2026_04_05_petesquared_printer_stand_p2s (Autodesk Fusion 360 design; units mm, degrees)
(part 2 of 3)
sketch "printer_shelf_top" plane through (0, 0, 0) normal (0, 0, 1) x axis (1, 0, 0)
  line L1 (214.249, 477.012) -> (-214.249, 477.012)
  line L2 (214.249, 0) -> (214.249, 477.012)
  line L3 (-214.249, 0) -> (214.249, 0)
  line L4 (-214.249, 477.012) -> (-214.249, 0)
  line L5 (-214.249, 7.62) -> (214.249, 7.62)
  line L6 (-214.249, 19.812) -> (214.249, 19.812)
  line L7 (203.2508, 15.24) -> (191.0588, 15.24)
  line L8 (203.2508, 477.012) -> (203.2508, 15.24)
  line L9 (191.0588, 477.012) -> (191.0588, 15.24)
  line L10 (0, 0) -> (0, 477.012)
  line L11 (-191.0588, 477.012) -> (-191.0588, 15.24)
  line L12 (-203.2508, 15.24) -> (-191.0588, 15.24)
  line L13 (-203.2508, 477.012) -> (-203.2508, 15.24)
  line L14 (203.2508, 246.126) -> (191.0588, 246.126)
  line L15 (-203.2508, 246.126) -> (-191.0588, 246.126)
  line L16 (214.249, 246.126) -> (191.0588, 246.126)
  line L17 (228.6, 0) -> (228.6, 508)
  line L18 (-127, 417.9654) -> (-127, 477.012)
  line L19 (-113.5296, 404.495) -> (-127, 417.9654)
  line L20 (113.5296, 404.495) -> (-113.5296, 404.495)
  line L21 (127, 417.9654) -> (113.5296, 404.495)
  line L22 (127, 417.9654) -> (127, 477.012)
  circle C1 centre (0, 13.716) radius 1.6002
  circle C2 centre (197.1548, 246.126) radius 1.6002
  circle C3 centre (-197.1548, 246.126) radius 1.6002
  circle C4 centre (197.1548, 68.326) radius 1.6002
  circle C5 centre (-197.1548, 68.326) radius 1.6002
  circle C6 centre (197.1548, 423.926) radius 1.6002
  circle C7 centre (-197.1548, 423.926) radius 1.6002
  circle C8 centre (-152.4, 13.716) radius 1.6002
  circle C9 centre (152.4, 13.716) radius 1.6002
  point P6 (0, 0)
  point P7 (0, 0)
  point P8 (214.249, 7.62)
  point P9 (-214.249, 7.62)
  point P10 (214.249, 19.812)
  point P11 (-214.249, 19.812)
  point P14 (203.2508, 477.012)
  point P15 (191.0588, 477.012)
  point P16 (0, 477.012)
  point P17 (0, 0)
  point P12 (191.0588, 15.24)
  point P18 (-191.0588, 15.24)
  point P13 (203.2508, 15.24)
  point P20 (-203.2508, 15.24)
  point P21 (-203.2508, 477.012)
  point P19 (-191.0588, 477.012)
  point P22 (-191.0588, 19.812)
  point P23 (191.0588, 19.812)
  point P24 (191.0588, 477.012)
  point P25 (0, 13.716)
  point P26 (191.0588, 246.126)
  point P27 (203.2508, 246.126)
  point P28 (197.1548, 246.126)
  point P29 (-191.0588, 246.126)
  point P30 (-203.2508, 246.126)
  point P31 (-197.1548, 246.126)
  point P33 (214.249, 246.126)
  point P32 (191.0588, 246.126)
  point P39 (-127, 477.012)
  point P42 (0, 404.495)
  point P38 (127, 477.012)
  point P50 (0, 398.145)
  point P4 (214.249, 0)
  point P5 (-214.249, 0)
  point P3 (214.249, 477.012)
  point P36 (-127, 417.9654)
  point P37 (-113.5296, 404.495)
  horizontal L1
  vertical L2
  horizontal L3
  vertical L4
  midpoint L3 P6
  vertical P6 P7
  coincident L2 P8
  coincident L4 P9
  perpendicular L4 L5
  coincident L2 P10
  coincident L4 P11
  perpendicular L4 L6
  parallel L6 L7
  coincident L1 P14
  perpendicular L1 L8
  coincident L1 P15
  perpendicular L1 L9
  midpoint L1 P16
  coincident P6 P17
  symmetric P12 L10 P18
  symmetric P13 L10 P20
  symmetric P14 L10 P21
  symmetric P15 L10 P19
  coincident L6 P22
  coincident L11 P22
  coincident L6 P23
  coincident L9 P23
  coincident P15 P24
  coincident L10 P25
  midpoint L9 P26
  midpoint L8 P27
  midpoint L14 P28
  midpoint L11 P29
  midpoint L13 P30
  midpoint L15 P31
  coincident L2 P33
  perpendicular L2 L16
  horizontal P27 P32
  horizontal L20
  equal L19 L21
  equal L18 L22
  coincident L1 P39
  midpoint L20 P42
  vertical P16 P42
  vertical L18
  vertical L22
  coincident L1 P38
  coincident L9 P32
  coincident P6 P7
  coincident L10 P50
  dimension "d58" distance P4 P5 = 428.498 (= "global_shelf_width")
  dimension "d419" distance P4 P8 = 7.62
  dimension "d420" distance P8 P10 = 12.192 (= "material_thickness")
  dimension "d428" distance L6 P13 = 4.572 (= "dado_material_depth")
  dimension "d429" distance P12 P13 = 12.192 (= "material_thickness")
  dimension "d1465" diameter C1 = 3.2004 (= "hole_screw")
  dimension "d1466" distance L5 P25 = 6.096 (= "material_thickness / 2")
  dimension "d1473" diameter C2 = 3.2004 (= "hole_screw")
  dimension "d1474" diameter C3 = 3.2004 (= "hole_screw")
  dimension "d1831" distance P13 L17 = 25.3492 (= "material_thickness + runner_thickness")
  dimension "d2388" distance P3 P10 = 457.2 (= "global_shelf_length")
  dimension "d2627" angle L19 L20 = 135
  dimension "d2628" distance P36 P37 = 19.05
  dimension "d3065" distance P16 P39 = 127
  dimension "d3073" distance L5 P50 = 390.525 (= "15 3/8")
  dimension "d3074" distance P42 P50 = 6.35
  dimension "d3014" R-Pattern1-uDistance = 0
  dimension "d3015" R-Pattern1-vDistance = 177.8
  dimension "d3018" R-Pattern2-uDistance = 152.4
  dimension "d3019" R-Pattern2-vDistance = 0
work_plane "WorkPlane4" RotateAngle 90
sketch "printer_shelf_front" plane through (0, 7.62, 0) normal (0, 1, 0) x axis (-1, 0, 0)
  line L1 (214.249, -53.848) -> (214.249, -7.62)
  line L2 (-214.249, -53.848) -> (-214.249, -7.62)
  line L3 (-48.9938, -34.798) -> (48.9938, -34.798)
  line L4 (-76.2, -53.848) -> (-192.7409, -53.848)
  line L5 (214.249, -53.848) -> (76.2, -53.848)
  line L6 (-76.2, -53.848) -> (-48.9938, -34.798)
  line L7 (76.2, -53.848) -> (48.9938, -34.798)
  line L8 (-192.7409, -53.848) -> (-214.249, -53.848)
  line L9 (-214.249, -7.62) -> (214.249, -7.62)
  line L10 (-23.85, -71.12) -> (1.35, -71.12)
  point P10 (76.2, -53.848)
  point P12 (0, -34.798)
  point P1 (0, 0)
  point P14 (76.2, -58.928)
  point P11 (48.9938, -34.798)
  point P13 (48.9938, -58.928)
  point P3 (214.249, -53.848)
  point P5 (-214.249, -53.848)
  point P4 (-214.249, -7.62)
  point P16 (-214.249, 0)
  point P2 (214.249, -7.62)
  point P15 (214.249, 0)
  point P7 (214.249, -53.848)
  point P8 (-76.2, -53.848)
  point P18 (-23.85, -71.12)
  horizontal L4
  horizontal L3
  coincident P10 L4
  midpoint L3 P12
  vertical P1 P12
  vertical P10 P14
  vertical P11 P13
  equal L6 L7
  vertical L1
  horizontal P3 P5
  horizontal L5
  vertical L2
  vertical P4 P16
  vertical P2 P15
  horizontal L9
  coincident P3 P7
  dimension "d697" distance L3 L4 = 19.05 (= "handle_inset_depth")
  dimension "d2625" distance P4 P16 = 7.62 (= "material_thickness - dado_material_depth")
  dimension "d2626" distance P8 P18 = 17.272 (= "material_thickness + 0.2 in")
extrude "Extrude17" new body sketch "printer_shelf_top" profile of L1 L2 L3 L4 L5 L6 L7 L8 L9 L11 L12 L13 C1 C2 C3 L18 L19 L20 L21 L22 no distance stored bodies "printer_shelf_top"
extrude "Extrude18" new body sketch "printer_shelf_front" profile of L1 L2 L5 L3 L6 L7 L8 L9 along normal blind 12.192 (= "material_thickness") bodies "printer_shelf_front"
extrude "Extrude19" cut sketch "printer_shelf_top" profile of L1 L2 L4 L5 L6 L7 L8 L9 L11 L12 L13 C1 C2 C3 along normal blind 4.572 (= "dado_material_depth")
extrude "Extrude21" new body sketch "printer_shelf_top" profile of L1 L6 L7 L8 L9 L11 L12 L13 C2 C3 to an object bodies "printer_shelf_support_left", "printer_shelf_support_right"
extrude "Extrude26" cut sketch "printer_shelf_top" profile of C1 C2 C3 C4 C5 C6 C7 C8 C9 to an object
combine "Combine4"
sketch "runner" plane through (203.2508, 0, 0) normal (1, 0, 0) x axis (0, 1, 0)
  line L1 (477.012, -7.62) -> (477.012, -53.848)
  line L2 (15.24, -7.62) -> (477.012, -7.62)
  line L3 (15.24, -53.848) -> (15.24, -7.62)
  line L4 (477.012, -53.848) -> (15.24, -53.848)
  line L5 (483.616, -13.335) -> (32.766, -13.335)
  line L6 (483.616, -58.928) -> (483.616, -13.335)
  line L7 (32.766, -58.928) -> (483.616, -58.928)
  line L8 (32.766, -13.335) -> (32.766, -58.928)
  line L9 (70.739, -35.4965) -> (89.789, -35.4965)
  line L10 (89.789, -36.7665) -> (70.739, -36.7665)
  line L11 (70.739, -36.7665) -> (89.789, -35.4965)
  line L12 (89.789, -36.7665) -> (70.739, -35.4965)
  line L13 (250.2535, -36.7665) -> (231.2035, -36.7665)
  line L14 (250.2535, -36.7665) -> (231.2035, -35.4965)
  line L15 (231.2035, -35.4965) -> (250.2535, -35.4965)
  line L16 (231.2035, -36.7665) -> (250.2535, -35.4965)
  line L17 (410.337, -36.7665) -> (391.287, -35.4965)
  line L18 (391.287, -36.7665) -> (410.337, -35.4965)
  line L19 (391.287, -35.4965) -> (410.337, -35.4965)
  line L20 (410.337, -36.7665) -> (391.287, -36.7665)
  circle C1 centre (37.846, -36.1315) radius 1.6002
  circle C2 centre (307.086, -36.1315) radius 1.6002
  circle C3 centre (473.456, -36.1315) radius 1.6002
  circle C4 centre (80.264, -36.1315) radius 1.6002
  circle C5 centre (240.7285, -36.1315) radius 1.6002
  circle C6 centre (400.812, -36.1315) radius 1.6002
  circle C7 centre (37.846, 573.4685) radius 1.6002
  circle C8 centre (307.086, 573.4685) radius 1.6002
  circle C9 centre (473.456, 573.4685) radius 1.6002
  point P9 (483.616, -58.928)
  point P11 (483.616, -58.928)
  point P12 (32.766, -36.1315)
  point P13 (37.846, -36.1315)
  point P14 (307.086, -36.1315)
  point P15 (473.456, -36.1315)
  point P21 (80.264, -36.1315)
  point P16 (80.264, -36.1315)
  point P26 (240.7285, -36.1315)
  point P18 (70.739, -35.4965)
  point P19 (70.739, -36.7665)
  point P17 (89.789, -35.4965)
  point P20 (89.789, -36.7665)
  point P22 (231.2035, -36.7665)
  point P24 (231.2035, -35.4965)
  point P23 (250.2535, -35.4965)
  point P25 (250.2535, -36.7665)
  point P27 (240.7285, -36.1315)
  point P30 (391.287, -35.4965)
  point P31 (391.287, -36.7665)
  point P29 (410.337, -35.4965)
  point P32 (410.337, -36.7665)
  point P33 (400.812, -36.1315)
  point P28 (400.812, -36.1315)
  point P7 (32.766, -13.335)
  point P10 (32.766, -58.928)
  point P8 (483.616, -13.335)
  horizontal L5
  vertical L6
  horizontal L7
  vertical L8
  coincident P9 P11
  midpoint L8 P12
  horizontal P12 P13
  horizontal P12 P14
  horizontal P12 P15
  horizontal L9
  parallel L9 L10
  coincident L11 P21
  coincident L12 P21
  coincident P16 P21
  horizontal P12 P16
  horizontal L15
  parallel L13 L15
  horizontal P12 P26
  vertical P18 P19
  vertical P17 P20
  vertical P22 P24
  vertical P23 P25
  midpoint L14 P27
  coincident P26 P27
  horizontal L19
  parallel L19 L20
  vertical P30 P31
  vertical P29 P32
  midpoint P33 L17
  coincident P28 P33
  horizontal P12 P28
  dimension "d3115" distance P7 P10 = 45.593
  dimension "d3116" distance P7 P8 = 450.85 (= "17 3/4")
  dimension "d3117" diameter C1 = 3.2004 (= "hole_screw")
  dimension "d3119" diameter C2 = 3.2004 (= "hole_screw")
  dimension "d3121" diameter C3 = 3.2004 (= "hole_screw")
  dimension "d3123" diameter C4 = 3.2004 (= "hole_screw")
  dimension "d3124" distance P17 P18 = 19.05
  dimension "d3125" distance P18 P19 = 1.27
  dimension "d3127" diameter C5 = 3.2004 (= "hole_screw")
  dimension "d3128" distance P23 P24 = 19.05
  dimension "d3129" distance P22 P24 = 1.27
  dimension "d3131" diameter C6 = 3.2004 (= "hole_screw")
  dimension "d3132" distance P29 P30 = 19.05
  dimension "d3133" distance P30 P31 = 1.27
  dimension "d3406" distance P8 P15 = 10.16
  dimension "d3407" distance P8 P14 = 176.53
  dimension "d3408" distance P8 P13 = 445.77
  dimension "d3409" distance P9 P28 = 82.804
  dimension "d3410" distance P9 P26 = 242.8875 (= "9 9/16")
  dimension "d3411" distance P9 P21 = 403.352
  dimension "d3609" R-Pattern1-uDistance = 0
  dimension "d3610" R-Pattern1-vDistance = 609.6 (= "printer_height_adjusted")
extrude "Extrude65" cut sketch "runner" profile of C1 C2 C3 C4 to an object offset -6.096 (= "-material_thickness / 2") Side2Offset -6.096 (= "-material_thickness / 2")
sketch "printer_shelf_feet_holes" plane through (0, 0, 0) normal (0, 0, 1) x axis (1, 0, 0)
  line L1 (193.675, 394.97) -> (-193.675, 394.97)
  line L2 (193.675, 7.62) -> (193.675, 394.97)
  line L3 (-193.675, 7.62) -> (193.675, 7.62)
  line L4 (-193.675, 394.97) -> (-193.675, 7.62)
  line L5 (0, 7.62) -> (0, 394.97)
  line L6 (193.675, 201.295) -> (-193.675, 201.295)
  line L7 (-214.249, 7.62) -> (214.249, 7.62)
  circle C1 centre (171.196, 30.099) radius 1.6002
  circle C2 centre (171.196, 30.099) radius 12.7
  circle C3 centre (-171.196, 30.099) radius 12.7
  circle C4 centre (-171.196, 30.099) radius 1.6002
  circle C5 centre (-171.196, 372.491) radius 12.7
  circle C6 centre (-171.196, 372.491) radius 1.6002
  circle C7 centre (171.196, 372.491) radius 1.6002
  circle C8 centre (171.196, 372.491) radius 12.7
  point P6 (0, 394.97)
  point P7 (0, 7.62)
  point P8 (-193.675, 201.295)
  point P9 (193.675, 201.295)
  point P10 (0, 201.295)
  point P11 (0, 0)
  point P4 (193.675, 7.62)
  point P5 (-193.675, 7.62)
  point P2 (-193.675, 394.97)
  point P15 (171.196, 30.099)
  point P14 (171.196, 30.099)
  horizontal L1
  vertical L2
  horizontal L3
  vertical L4
  midpoint L1 P6
  midpoint L3 P7
  midpoint L4 P8
  midpoint L2 P9
  midpoint L6 P10
  vertical P10 P11
  coincident P4 L7
  concentric C1 C2
  symmetric L5 C1 C4
  symmetric L5 C2 C3
  symmetric L6 C1 C7
  symmetric L6 C2 C8
  symmetric L6 C3 C5
  symmetric L6 C4 C6
  dimension "d3144" distance P4 P5 = 387.35
  dimension "d3145" distance P2 P5 = 387.35
  dimension "d3147" diameter C1 = 3.2004 (= "hole_screw")
  dimension "d3148" diameter C2 = 25.4
  dimension "d3149" distance P4 P15 = 22.479
  dimension "d3150" distance P4 P14 = 22.479
extrude "Extrude24" cut sketch "printer_shelf_feet_holes" profile of C1 C4 C6 C7 no distance stored
extrude "Extrude23" cut sketch "runner" profile of C1 C4 C5 C6 no distance stored
sketch "printer_shelf_holes_screw_slides" plane through (203.2508, 0, 0) normal (1, 0, 0) x axis (0, 1, 0)
  line L1 (477.012, -7.62) -> (477.012, -53.848)
  line L2 (15.24, -7.62) -> (477.012, -7.62)
  line L3 (15.24, -53.848) -> (15.24, -7.62)
  line L4 (477.012, -53.848) -> (15.24, -53.848)
  circle C1 centre (216.154, -38.608) radius 1.6002
  circle C2 centre (73.914, -38.608) radius 1.6002
  circle C3 centre (404.114, -38.608) radius 1.6002
  circle C4 centre (80.264, -36.1315) radius 1.6002
  circle C5 centre (240.7285, -36.1315) radius 1.6002
  circle C6 centre (400.812, -36.1315) radius 1.6002
  point P8 (73.914, -38.608)
  point P9 (216.154, -38.608)
  point P10 (404.114, -38.608)
  point P6 (15.24, -53.848)
  horizontal P8 P9
  horizontal P8 P10
  dimension "d3031" diameter C2 = 3.2004 (= "hole_screw")
  dimension "d3034" diameter C1 = 3.2004 (= "hole_screw")
  dimension "d3036" diameter C3 = 3.2004 (= "hole_screw")
  dimension "d3038" distance P6 P8 = 15.24
  dimension "d3039" distance P6 P8 = 58.674
  dimension "d3040" distance P6 P9 = 200.914
  dimension "d3041" distance P6 P10 = 388.874
work_plane "WorkPlane3" AlongDistance 355.6 (= "ams_height_adjusted")
sketch "ams_side_right" plane through (228.6, 0, 0) normal (1, 0, 0) x axis (0, 1, 0)
  line L1 (508, 894.08) -> (0, 894.08)
  line L2 (508, 538.48) -> (508, 894.08)
  line L3 (0, 538.48) -> (508, 538.48)
  line L4 (-1.35, 538.48) -> (23.85, 538.48)
  line L5 (508, -402.336) -> (508, 402.336)
  line L6 (0, 85.5947) -> (0, 2.9515)
  line L7 (431.8, 817.88) -> (76.2, 817.88)
  line L8 (431.8, 614.68) -> (431.8, 817.88)
  line L9 (76.2, 614.68) -> (431.8, 614.68)
  line L10 (76.2, 817.88) -> (76.2, 614.68)
  line L11 (76.2, 741.68) -> (0, 817.88)
  line L12 (76.2, 690.88) -> (76.2, 741.68)
  line L13 (508, 538.48) -> (0, 894.08)
  line L14 (508, 894.08) -> (0, 538.48)
  line L15 (280.309, 654.05) -> (187.325, 747.034)
  line L16 (352.151, 654.05) -> (201.021, 805.18)
  line L17 (142.875, 747.034) -> (187.325, 747.034)
  line L18 (142.875, 641.0309) -> (142.875, 747.034)
  line L19 (174.3059, 609.6) -> (142.875, 641.0309)
  line L20 (280.309, 609.6) -> (174.3059, 609.6)
  line L21 (280.309, 654.05) -> (280.309, 609.6)
  line L22 (0, 614.68) -> (76.2, 690.88)
  line L23 (0, 614.68) -> (0, 538.48)
  line L24 (0, 894.08) -> (0, 817.88)
  line L25 (483.616, 654.05) -> (352.151, 654.05)
  line L26 (483.616, 696.214) -> (483.616, 654.05)
  line L27 (330.2, 849.63) -> (483.616, 696.214)
  line L28 (201.021, 849.63) -> (330.2, 849.63)
  line L29 (201.021, 805.18) -> (201.021, 849.63)
  line L30 (12.192, 550.672) -> (12.192, 538.48)
  line L31 (139.7, 550.672) -> (12.192, 550.672)
  line L32 (139.7, 538.48) -> (139.7, 550.672)
  line L33 (360.68, 550.672) -> (360.68, 538.48)
  line L34 (500.38, 550.672) -> (360.68, 550.672)
  line L35 (500.38, 538.48) -> (500.38, 550.672)
  line L36 (495.808, 881.888) -> (495.808, 550.672)
  line L37 (12.192, 881.888) -> (12.192, 894.08)
  line L38 (139.7, 881.888) -> (12.192, 881.888)
  line L39 (139.7, 894.08) -> (139.7, 881.888)
  line L40 (360.68, 881.888) -> (360.68, 894.08)
  line L41 (500.38, 881.888) -> (360.68, 881.888)
  line L42 (500.38, 894.08) -> (500.38, 881.888)
  line L43 (495.808, 716.28) -> (508, 716.28)
  line L44 (483.616, 822.96) -> (483.616, 881.888)
  line L45 (495.808, 822.96) -> (483.616, 822.96)
  line L46 (483.616, 467.36) -> (483.616, 526.288)
  line L47 (483.616, 609.6) -> (483.616, 550.672)
  line L48 (495.808, 609.6) -> (483.616, 609.6)
  circle C1 centre (76.2, 817.88) radius 5.207
  circle C2 centre (76.2, 817.88) radius 8.128
  circle C3 centre (76.2, 614.68) radius 5.207
  circle C4 centre (76.2, 614.68) radius 8.128
  circle C5 centre (431.8, 817.88) radius 5.207
  circle C6 centre (431.8, 817.88) radius 8.128
  circle C7 centre (431.8, 614.68) radius 8.128
  circle C8 centre (431.8, 614.68) radius 5.207
  circle C9 centre (37.592, 544.576) radius 1.6002
  circle C10 centre (114.3, 544.576) radius 1.6002
  circle C11 centre (386.08, 544.576) radius 1.6002
  circle C12 centre (470.408, 544.576) radius 1.6002
  circle C13 centre (37.592, 887.984) radius 1.6002
  circle C14 centre (114.3, 887.984) radius 1.6002
  circle C15 centre (386.08, 887.984) radius 1.6002
  circle C16 centre (474.98, 887.984) radius 1.6002
  circle C17 centre (501.904, 716.28) radius 1.6002
  circle C18 centre (501.904, 567.69) radius 1.6002
  circle C19 centre (501.904, 864.87) radius 1.6002
  circle C20 centre (489.712, 839.8933) radius 1.6002
  circle C21 centre (489.712, 864.9547) radius 1.6002
  circle C22 centre (489.712, 592.6667) radius 1.6002
  circle C23 centre (489.712, 563.372) radius 1.6002
  point P4 (508, 538.48)
  point P8 (508, 402.336)
  point P5 (0, 538.48)
  point P11 (0, 85.5947)
  point P12 (76.2, 817.88)
  point P16 (76.2, 817.88)
  point P15 (76.2, 614.68)
  point P18 (76.2, 614.68)
  point P13 (431.8, 817.88)
  point P20 (431.8, 817.88)
  point P14 (431.8, 614.68)
  point P22 (431.8, 614.68)
  point P25 (76.2, 741.68)
  point P29 (201.021, 805.18)
  point P40 (201.021, 805.18)
  point P41 (254, 716.28)
  point P28 (280.309, 654.05)
  point P30 (352.151, 654.05)
  point P42 (12.192, 538.48)
  point P45 (139.7, 538.48)
  point P46 (360.68, 538.48)
  point P49 (500.38, 538.48)
  point P50 (495.808, 550.672)
  point P53 (12.192, 894.08)
  point P56 (139.7, 894.08)
  point P57 (360.68, 894.08)
  point P51 (495.808, 881.888)
  point P60 (500.38, 894.08)
  point P17 (76.2, 817.88)
  point P24 (0, 817.88)
  point P19 (76.2, 614.68)
  point P35 (0, 614.68)
  point P62 (12.192, 544.576)
  point P63 (37.592, 544.576)
  point P64 (114.3, 544.576)
  point P66 (500.38, 544.576)
  point P65 (386.08, 544.576)
  point P67 (470.408, 544.576)
  point P68 (12.192, 887.984)
  point P69 (360.68, 887.984)
  point P70 (37.592, 887.984)
  point P71 (114.3, 887.984)
  point P72 (386.08, 887.984)
  point P73 (474.98, 887.984)
  point P74 (508, 716.28)
  point P75 (495.808, 716.28)
  point P76 (501.904, 716.28)
  point P77 (501.904, 716.28)
  point P80 (483.616, 881.888)
  point P82 (495.808, 822.96)
  point P85 (489.712, 822.96)
  point P86 (489.712, 839.8933)
  point P87 (489.712, 864.9547)
  point P88 (483.616, 550.672)
  point P90 (495.808, 609.6)
  point P91 (489.712, 609.6)
  point P92 (489.712, 592.6667)
  point P93 (489.712, 563.372)
  point P2 (0, 894.08)
  point P38 (330.2, 849.63)
  point P27 (187.325, 747.034)
  point P31 (142.875, 747.034)
  point P39 (201.021, 849.63)
  point P34 (280.309, 609.6)
  point P32 (142.875, 641.0309)
  point P33 (174.3059, 609.6)
  point P61 (0, 538.48)
  point P43 (12.192, 550.672)
  point P47 (360.68, 550.672)
  point P48 (500.38, 550.672)
  point P52 (508, 538.48)
  point P55 (139.7, 881.888)
  point P58 (360.68, 881.888)
  point P3 (508, 894.08)
  point P59 (500.38, 881.888)
  point P44 (139.7, 550.672)
  point P81 (483.616, 822.96)
  point P89 (483.616, 609.6)
  horizontal L1
  vertical L2
  horizontal L3
  vertical L23
  vertical P4 P8
  collinear L3 L4
  vertical P5 P11
  horizontal L7
  vertical L8
  horizontal L9
  vertical L10
  coincident P12 P16
  concentric C1 C2
  coincident P15 P18
  concentric C3 C4
  coincident P13 P20
  concentric C5 C6
  coincident P14 P22
  concentric C7 C8
  parallel L12 L23
  coincident L10 P25
  parallel L9 L17
  parallel L17 L20
  vertical L21
  vertical L18
  collinear L23 L24
  parallel L15 L16
  horizontal L25
  perpendicular L25 L26
  perpendicular L26 L28
  perpendicular L28 L29
  coincident P29 P40
  parallel L16 L27
  midpoint L14 P41
  horizontal P28 P30
  coincident L3 P42
  perpendicular L3 L30
  perpendicular L30 L31
  coincident L3 P45
  perpendicular L3 L32
  coincident L3 P46
  perpendicular L3 L33
  perpendicular L33 L34
  coincident L3 P49
  perpendicular L3 L35
  coincident L34 P50
  perpendicular L34 L36
  coincident L1 P53
  perpendicular L1 L37
  perpendicular L37 L38
  coincident L1 P56
  perpendicular L1 L39
  coincident L1 P57
  perpendicular L1 L40
  perpendicular L2 L41
  coincident P51 L41
  coincident L1 P60
  perpendicular L1 L42
  horizontal P17 P24
  horizontal P19 P35
  midpoint L30 P62
  horizontal P62 P63
  horizontal P62 P64
  midpoint L35 P66
  horizontal P65 P66
  horizontal P66 P67
  midpoint L37 P68
  midpoint L40 P69
  horizontal P68 P70
  horizontal P68 P71
  horizontal P72 P73
  horizontal P69 P73
  midpoint L2 P74
  midpoint L36 P75
  midpoint L43 P76
  coincident P76 P77
  coincident L41 P80
  perpendicular L41 L44
  coincident L36 P82
  perpendicular L36 L45
  equal L44 L46
  midpoint L45 P85
  vertical P86 P87
  vertical P85 P87
  coincident L34 P88
  perpendicular L34 L47
  perpendicular L47 L48
  coincident L36 P90
  midpoint L48 P91
  vertical P91 P92
  vertical P91 P93
  equal L44 L47
  dimension "d2723" distance P2 P5 = 355.6 (= "ams_height_adjusted")
  dimension "d2724" diameter C1 = 10.414 (= "hole_bolt")
  dimension "d2725" diameter C2 = 16.256 (= "dado_bolthead_diameter")
  dimension "d2726" diameter C3 = 10.414 (= "hole_bolt")
  dimension "d2727" diameter C4 = 16.256 (= "dado_bolthead_diameter")
  dimension "d2728" distance L10 L23 = 76.2 (= "bolt_side_offset")
  dimension "d2730" distance L1 L7 = 76.2 (= "bolt_side_offset")
  dimension "d2731" distance L2 L8 = 76.2 (= "bolt_side_offset")
  dimension "d2732" distance L3 L9 = 76.2 (= "bolt_side_offset")
  dimension "d2733" diameter C5 = 10.414 (= "hole_bolt")
  dimension "d2734" diameter C6 = 16.256 (= "dado_bolthead_diameter")
  dimension "d2735" diameter C7 = 16.256 (= "dado_bolthead_diameter")
  dimension "d2736" diameter C8 = 10.414 (= "hole_bolt")
  dimension "d2741" angle L19 L20 = 135
  dimension "d2745" distance L10 L18 = 66.675 (= "global_cutout_padding * 1.5")
  dimension "d2746" distance L3 L20 = 71.12 (= "global_shelf_height")
  dimension "d2747" angle L10 L11 = 135
  dimension "d2748" angle L10 L22 = 135
  dimension "d2752" distance L1 L28 = 44.45 (= "global_cutout_padding")
  dimension "d2754" distance L2 L26 = 24.384 (= "material_thickness * 2")
  dimension "d2756" distance L2 P38 = 177.8 (= "global_cutout_padding * 4")
  dimension "d2757" distance L15 P41 = 25.4
  dimension "d2758" distance L16 P41 = 25.4
  dimension "d2759" angle L15 L17 = 135
  dimension "d2760" distance P27 P31 = 44.45 (= "global_cutout_padding")
  dimension "d2761" distance P39 P40 = 44.45 (= "global_cutout_padding")
  dimension "d2763" distance P28 P34 = 44.45 (= "global_cutout_padding")
  dimension "d2764" distance P32 P33 = 44.45 (= "global_cutout_padding")
  dimension "d2770" distance P45 P61 = 139.7 (= "brace_length")
  dimension "d2771" distance P42 P43 = 12.192 (= "material_thickness")
  dimension "d2772" distance P5 P42 = 12.192 (= "material_thickness")
  dimension "d2773" distance P46 P47 = 12.192 (= "material_thickness")
  dimension "d2774" distance P48 P52 = 7.62 (= "material_thickness - dado_material_depth")
  dimension "d2775" distance P50 P52 = 12.192 (= "material_thickness")
  dimension "d2777" distance P55 P56 = 12.192 (= "material_thickness")
  dimension "d2778" distance P2 P55 = 139.7 (= "brace_length")
  dimension "d2779" distance P2 P53 = 12.192 (= "material_thickness")
  dimension "d2780" distance P57 P58 = 12.192 (= "material_thickness")
  dimension "d2782" distance P3 P59 = 7.62 (= "material_thickness - dado_material_depth")
  dimension "d3425" distance P47 P50 = 135.128 (= "brace_length - dado_material_depth")
  dimension "d3426" distance P51 P58 = 135.128 (= "brace_length - dado_material_depth")
  dimension "d3427" diameter C9 = 3.2004 (= "hole_screw")
  dimension "d3428" distance P62 P63 = 25.4 (= "hole_screw_brace_offset")
  dimension "d3429" diameter C10 = 3.2004 (= "hole_screw")
  dimension "d3430" distance P44 P64 = 25.4 (= "hole_screw_brace_offset")
  dimension "d3431" diameter C11 = 3.2004 (= "hole_screw")
  dimension "d3432" diameter C12 = 3.2004 (= "hole_screw")
  dimension "d3434" distance P50 P67 = 25.4 (= "hole_screw_brace_offset")
  dimension "d3435" distance P47 P65 = 25.4 (= "hole_screw_brace_offset")
  dimension "d3436" diameter C13 = 3.2004 (= "hole_screw")
  dimension "d3437" diameter C14 = 3.2004 (= "hole_screw")
  dimension "d3438" distance P68 P70 = 25.4 (= "hole_screw_brace_offset")
  dimension "d3439" distance P56 P71 = 25.4 (= "hole_screw_brace_offset")
  dimension "d3440" diameter C15 = 3.2004 (= "hole_screw")
  dimension "d3441" diameter C16 = 3.2004 (= "hole_screw")
  dimension "d3442" distance P69 P72 = 25.4 (= "hole_screw_brace_offset")
  dimension "d3443" distance P60 P73 = 25.4 (= "hole_screw_brace_offset")
  dimension "d3444" diameter C17 = 3.2004 (= "hole_screw")
  dimension "d3449" distance P81 P82 = 12.192 (= "material_thickness")
  dimension "d3451" diameter C20 = 3.2004 (= "hole_screw")
  dimension "d3452" diameter C21 = 3.2004 (= "hole_screw")
  dimension "d3453" distance P85 P86 = 16.9333 (= "hole_screw_brace_offset / 1.5")
  dimension "d3454" distance P51 P87 = 16.9333 (= "hole_screw_brace_offset / 1.5")
  dimension "d3461" distance P89 P90 = 12.192 (= "material_thickness")
  dimension "d3462" diameter C22 = 3.2004 (= "hole_screw")
  dimension "d3463" diameter C23 = 3.2004 (= "hole_screw")
  dimension "d3464" distance P91 P92 = 16.9333 (= "hole_screw_brace_offset / 1.5")
  dimension "d3465" distance P50 P93 = 12.7 (= "hole_screw_brace_offset / 2")
  dimension "d3447" R-Pattern1-uDistance = 0
  dimension "d3448" R-Pattern1-vDistance = 148.59
extrude "Extrude23" new body sketch "ams_side_right" profile of L1 L2 L3 L24 C1 C2 C3 C4 C5 C6 C7 C8 L11 L12 L15 L16 L17 L18 L19 L20 L21 L22 L25 L26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 no distance stored bodies "ams_side_left"
extrude "Extrude25" sketch "ams_side_right" profile of L1 L2 L3 L30 L31 L32 L33 L34 L35 L36 L37 L38 L39 L40 L41 L42 C9 C10 C11 C12 C13 C14 C15 C16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 blind 4.572 (= "dado_material_depth")
extrude "Extrude28" sketch "ams_side_right" profile of C1 C2 C3 C4 C5 C6 C7 C8 blind 4.572 (= "dado_material_depth")
work_plane "WorkPlane4"
mirror "Mirror3" mirrorStitchTolerance 0.1016 bodies "ams_side_right"
extrude "Extrude1" new body sketch "runner" profile of L1 L4 L5 L6 L7 L8 C1 C2 C3 C4 C5 C6 along normal blind 13.1572 (= "runner_thickness") bodies "runner_right"
fillet "Fillet1" radius 1.27
copy_paste_bodies "CopyPasteBodies2"
move "Move1"
sketch "base_side_right" plane through (228.6, 0, 0) normal (1, 0, 0) x axis (0, 1, 0)
  line L1 (508, -71.12) -> (0, -71.12)
  line L2 (508, -109.22) -> (508, -71.12)
  line L3 (0, -109.22) -> (508, -109.22)
  line L4 (0, -71.12) -> (0, -109.22)
  line L5 (-1.35, -71.12) -> (23.85, -71.12)
  line L6 (0, 85.5947) -> (0, 2.9515)
  line L7 (508, -402.336) -> (508, 402.336)
  line L8 (12.192, -83.312) -> (12.192, -71.12)
  line L9 (139.7, -83.312) -> (12.192, -83.312)
  line L10 (139.7, -71.12) -> (139.7, -83.312)
  line L11 (360.68, -83.312) -> (360.68, -71.12)
  line L12 (495.808, -83.312) -> (360.68, -83.312)
  line L13 (495.808, -71.12) -> (495.808, -83.312)
  line L14 (495.808, -109.22) -> (495.808, -83.312)
  line L15 (18.542, -109.22) -> (18.542, -83.312)
  line L16 (30.734, -109.22) -> (30.734, -83.312)
  line L17 (102.362, -95.504) -> (102.362, -83.312)
  line L18 (26.162, -95.504) -> (102.362, -95.504)
  line L19 (26.162, -83.312) -> (26.162, -95.504)
  line L20 (102.362, -83.312) -> (26.162, -83.312)
  line L21 (424.18, -95.504) -> (424.18, -83.312)
  line L22 (500.38, -95.504) -> (424.18, -95.504)
  line L23 (500.38, -83.312) -> (500.38, -95.504)
  line L24 (424.18, -83.312) -> (500.38, -83.312)
  circle C1 centre (114.3, -77.216) radius 1.6002
  circle C2 centre (37.592, -77.216) radius 1.6002
  circle C3 centre (386.08, -77.216) radius 1.6002
  circle C4 centre (470.408, -77.216) radius 1.6002
  circle C5 centre (76.962, -89.408) radius 1.6002
  circle C6 centre (43.0953, -89.408) radius 1.6002
  circle C7 centre (449.58, -89.408) radius 1.6002
  circle C8 centre (474.98, -89.408) radius 1.6002
  point P2 (0, -71.12)
  point P8 (0, 2.9515)
  point P4 (508, -109.22)
  point P12 (12.192, -71.12)
  point P15 (139.7, -71.12)
  point P16 (360.68, -71.12)
  point P19 (495.808, -71.12)
  point P20 (495.808, -109.22)
  point P21 (139.7, -77.216)
  point P22 (114.3, -77.216)
  point P23 (37.592, -77.216)
  point P26 (360.68, -77.216)
  point P24 (386.08, -77.216)
  point P25 (470.408, -77.216)
  point P27 (18.542, -83.312)
  point P28 (18.542, -109.22)
  point P29 (30.734, -83.312)
  point P30 (30.734, -109.22)
  point P32 (102.362, -83.312)
  point P36 (102.362, -89.408)
  point P37 (76.962, -89.408)
  point P38 (43.0953, -89.408)
  point P39 (424.18, -83.312)
  point P43 (424.18, -83.312)
  point P44 (424.18, -89.408)
  point P31 (500.38, -83.312)
  point P42 (500.38, -83.312)
  point P45 (449.58, -89.408)
  point P46 (474.98, -89.408)
  point P3 (508, -71.12)
  point P14 (139.7, -83.312)
  point P18 (495.808, -83.312)
  point P13 (12.192, -83.312)
  point P17 (360.68, -83.312)
  point P34 (26.162, -95.504)
  point P33 (102.362, -95.504)
  point P40 (424.18, -95.504)
  point P41 (500.38, -95.504)
  horizontal L1
  vertical L2
  horizontal L3
  vertical L4
  vertical P2 P8
  coincident P2 L5
  coincident P4 L7
  coincident L1 P12
  perpendicular L1 L8
  perpendicular L8 L9
  coincident L1 P15
  perpendicular L1 L10
  coincident L1 P16
  perpendicular L1 L11
  perpendicular L11 L12
  coincident L1 P19
  perpendicular L1 L13
  coincident L3 P20
  perpendicular L3 L14
  midpoint L10 P21
  horizontal P21 P22
  horizontal P21 P23
  midpoint L11 P26
  horizontal P24 P26
  horizontal P25 P26
  coincident L9 P27
  coincident L3 P28
  perpendicular L3 L15
  coincident L9 P29
  coincident L3 P30
  perpendicular L3 L16
  coincident L9 P32
  perpendicular L9 L17
  perpendicular L16 L18
  perpendicular L9 L19
  horizontal L20
  midpoint L17 P36
  horizontal P36 P37
  horizontal P36 P38
  perpendicular L12 L21
  perpendicular L14 L22
  perpendicular L12 L23
  perpendicular L21 L24
  coincident P39 P43
  midpoint L21 P44
  vertical P31 P42
  coincident P31 P42
  horizontal P44 P45
  horizontal P44 P46
  dimension "d2654" distance P3 P4 = 38.1 (= "base_height")
  dimension "d2655" distance P14 P15 = 12.192 (= "material_thickness")
  dimension "d2656" distance P2 P12 = 12.192 (= "material_thickness")
  dimension "d2658" distance L4 P14 = 139.7 (= "brace_length")
  dimension "d2659" distance P18 P19 = 12.192 (= "material_thickness")
  dimension "d2661" distance L2 P18 = 12.192 (= "material_thickness")
  dimension "d2662" diameter C1 = 3.2004 (= "hole_screw")
  dimension "d2663" diameter C2 = 3.2004 (= "hole_screw")
  dimension "d2664" distance P21 P22 = 25.4
  dimension "d2665" distance L8 P23 = 25.4
  dimension "d2666" diameter C3 = 3.2004 (= "hole_screw")
  dimension "d2667" diameter C4 = 3.2004 (= "hole_screw")
  dimension "d2668" distance P24 P26 = 25.4
  dimension "d2669" distance L13 P25 = 25.4
  dimension "d2690" distance P28 P30 = 12.192 (= "material_thickness")
  dimension "d2713" distance P13 P27 = 6.35
  dimension "d3501" distance P17 P31 = 139.7 (= "brace_length")
  dimension "d3526" distance P30 P34 = 4.572 (= "dado_material_depth")
  dimension "d3527" distance P32 P33 = 12.192 (= "material_thickness")
  dimension "d3528" distance P33 P34 = 76.2
  dimension "d3529" diameter C5 = 3.2004 (= "hole_screw")
  dimension "d3530" distance P36 P37 = 25.4 (= "hole_screw_brace_offset")
  dimension "d3531" diameter C6 = 3.2004 (= "hole_screw")
  dimension "d3532" distance P34 P38 = 16.9333 (= "hole_screw_brace_offset / 1.5")
  dimension "d3533" distance P39 P40 = 12.192 (= "material_thickness")
  dimension "d3534" distance P40 P41 = 76.2
  dimension "d3535" diameter C7 = 3.2004 (= "hole_screw")
  dimension "d3536" distance P44 P45 = 25.4 (= "hole_screw_brace_offset")
  dimension "d3537" diameter C8 = 3.2004 (= "hole_screw")
  dimension "d3538" distance P41 P46 = 25.4 (= "hole_screw_brace_offset")
extrude "Extrude28" new body sketch "base_side_right" profile of L1 L2 L3 L4 L5 L7 L8 L9 L10 L11 L12 L13 L14 C1 C2 C3 C4 L15 L16 L17 L18 L19 L20 C5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 no distance stored bodies "base_side_right"
extrude "Extrude29" sketch "base_side_right" profile of L1 L2 L3 L5 L7 L8 L9 L10 L11 L12 L13 L14 C1 C2 C3 C4 L15 L16 L17 L18 L19 L20 C5 C6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 blind 4.572 (= "dado_material_depth")
sketch "base_back" plane through (0, 508, 0) normal (0, 1, 0) x axis (1, 0, 0)
  line L1 (-228.6, 71.12) -> (228.6, 71.12)
  line L2 (-228.6, 109.22) -> (-228.6, 71.12)
  line L3 (228.6, 109.22) -> (-228.6, 109.22)
  line L4 (228.6, 71.12) -> (228.6, 109.22)
  line L5 (220.98, 83.312) -> (220.98, 109.22)
  line L6 (81.28, 83.312) -> (220.98, 83.312)
  line L7 (81.28, 71.12) -> (81.28, 83.312)
  line L8 (-220.98, 83.312) -> (-220.98, 109.22)
  line L9 (-81.28, 83.312) -> (-220.98, 83.312)
  line L10 (-81.28, 71.12) -> (-81.28, 83.312)
  line L11 (220.98, 71.12) -> (220.98, 83.312)
  line L12 (-220.98, 71.12) -> (-220.98, 83.312)
  line L13 (0, 71.12) -> (0, 109.22)
  line L14 (144.78, 95.504) -> (144.78, 83.312)
  line L15 (220.98, 95.504) -> (144.78, 95.504)
  line L16 (-144.78, 95.504) -> (-144.78, 83.312)
  line L17 (-220.98, 95.504) -> (-144.78, 95.504)
  circle C1 centre (106.68, 77.216) radius 1.6002
  circle C2 centre (195.58, 77.216) radius 1.6002
  circle C3 centre (-106.68, 77.216) radius 1.6002
  circle C4 centre (-195.58, 77.216) radius 1.6002
  circle C5 centre (170.18, 89.408) radius 1.6002
  circle C6 centre (195.58, 89.408) radius 1.6002
  circle C7 centre (-170.18, 89.408) radius 1.6002
  circle C8 centre (-195.58, 89.408) radius 1.6002
  point P6 (220.98, 109.22)
  point P9 (81.28, 71.12)
  point P10 (-220.98, 109.22)
  point P13 (-81.28, 71.12)
  point P2 (228.6, 71.12)
  point P14 (228.6, 71.12)
  point P5 (228.6, 109.22)
  point P15 (228.6, 109.22)
  point P8 (81.28, 83.312)
  point P12 (-81.28, 83.312)
  point P16 (220.98, 71.12)
  point P17 (-220.98, 71.12)
  point P18 (81.28, 77.216)
  point P19 (106.68, 77.216)
  point P20 (195.58, 77.216)
  point P21 (0, 109.22)
  point P22 (0, 71.12)
  point P27 (220.98, 95.504)
  point P25 (144.78, 83.312)
  point P28 (144.78, 89.408)
  point P29 (170.18, 89.408)
  point P30 (195.58, 89.408)
  point P31 (-144.78, 83.312)
  point P26 (144.78, 95.504)
  point P32 (-144.78, 95.504)
  point P33 (-220.98, 95.504)
  point P3 (-228.6, 71.12)
  point P4 (-228.6, 109.22)
  point P7 (220.98, 83.312)
  point P11 (-220.98, 83.312)
  horizontal L1
  vertical L2
  horizontal L3
  vertical L4
  coincident L3 P6
  perpendicular L3 L5
  perpendicular L5 L6
  coincident L1 P9
  perpendicular L1 L7
  coincident L3 P10
  perpendicular L3 L8
  perpendicular L8 L9
  coincident L1 P13
  perpendicular L1 L10
  coincident P2 P14
  coincident P5 P15
  horizontal P8 P12
  coincident L1 P16
  perpendicular L1 L11
  coincident L1 P17
  perpendicular L1 L12
  midpoint L7 P18
  horizontal P18 P19
  horizontal P18 P20
  midpoint L3 P21
  midpoint L1 P22
  symmetric C1 L13 C3
  symmetric C2 L13 C4
  perpendicular L6 L14
  perpendicular L14 L15
  coincident L5 P27
  coincident L6 P25
  midpoint L14 P28
  horizontal P28 P29
  horizontal P28 P30
  symmetric L13 P25 P31
  symmetric L13 P26 P32
  symmetric L13 P27 P33
  symmetric L13 C5 C7
  symmetric L13 C6 C8
  dimension "d2675" distance P5 P6 = 7.62 (= "material_thickness - dado_material_depth")
  dimension "d2676" distance P2 P3 = 457.2 (= "printer_width_adjusted")
  dimension "d2678" distance P4 P10 = 7.62 (= "material_thickness - dado_material_depth")
  dimension "d2680" distance P8 P9 = 12.192 (= "material_thickness")
  dimension "d3502" distance P7 P8 = 139.7 (= "brace_length")
  dimension "d3503" distance P11 P12 = 139.7 (= "brace_length")
  dimension "d3504" diameter C1 = 3.2004 (= "hole_screw")
  dimension "d3505" distance P18 P19 = 25.4 (= "hole_screw_brace_offset")
  dimension "d3506" diameter C2 = 3.2004 (= "hole_screw")
  dimension "d3507" distance P7 P20 = 25.4 (= "hole_screw_brace_offset")
  dimension "d3539" distance P25 P26 = 12.192 (= "material_thickness")
  dimension "d3540" distance P26 P27 = 76.2
  dimension "d3541" diameter C5 = 3.2004 (= "hole_screw")
  dimension "d3542" distance P28 P29 = 25.4 (= "hole_screw_brace_offset")
  dimension "d3543" diameter C6 = 3.2004 (= "hole_screw")
  dimension "d3544" distance P27 P30 = 25.4 (= "hole_screw_brace_offset")
extrude "Extrude30" new body sketch "base_back" profile of L1 L3 L5 L6 L7 L8 L9 L10 L11 L12 C1 C2 C3 C4 L14 L15 C5 C6 L16 L17 C7 C8 no distance stored bodies "base_back"
extrude "Extrude31" sketch "base_back" profile of L1 L5 L6 L7 L8 L9 L10 L11 L12 C1 C2 C3 C4 L14 L15 C5 C6 L16 L17 C7 C8 blind 4.572 (= "dado_material_depth")
mirror "Mirror6" mirrorStitchTolerance 0.1016 bodies "base_side_left"
sketch "base_front_brace" plane through (0, 30.734, 0) normal (0, -1, 0) x axis (1, 0, 0)
  line L1 (216.408, -109.22) -> (216.408, -95.504)
  line L2 (220.98, -109.22) -> (216.408, -109.22)
  line L3 (220.98, -95.504) -> (220.98, -109.22)
  line L4 (220.98, -78.74) -> (88.9, -78.74)
  line L5 (220.98, -109.22) -> (220.98, -78.74)
  line L6 (216.408, -109.22) -> (220.98, -109.22)
  line L7 (88.9, -97.79) -> (216.408, -109.22)
  line L8 (88.9, -78.74) -> (88.9, -97.79)
  line L9 (216.408, -95.504) -> (220.98, -95.504)
  point P4 (220.98, -109.22)
  point P8 (220.98, -109.22)
  point P7 (220.98, -78.74)
  point P11 (228.6, -83.312)
  point P6 (88.9, -78.74)
  point P10 (88.9, -97.79)
  point P9 (216.408, -109.22)
  horizontal L4
  perpendicular L4 L5
  perpendicular L5 L6
  perpendicular L4 L8
  coincident P4 P8
  dimension "d2714" distance P7 P11 = 4.572 (= "dado_material_depth")
  dimension "d2716" distance P6 P11 = 139.7 (= "brace_length")
  dimension "d2717" distance P6 P10 = 19.05
  dimension "d2718" distance P8 P9 = 4.572 (= "dado_material_depth")
extrude "Extrude32" new body sketch "base_front_brace" profile of L1 L2 L3 L4 L5 L6 L7 L8 along normal blind 12.446 (= "dado_material_thickness") bodies "base_bracket_front_right"
mirror "Mirror7" mirrorStitchTolerance 0.1016 bodies "base_bracket_front_left"
sketch "base_back_holes_screws" plane through (0, 508, 0) normal (0, 1, 0) x axis (1, 0, 0)
  line L1 (81.28, 71.12) -> (81.28, 83.312)
  line L2 (0, -2.5) -> (0, -20)
  circle C1 centre (106.68, 77.216) radius 1.6002
  circle C2 centre (195.58, 77.216) radius 1.6002
  circle C3 centre (-195.58, 77.216) radius 1.6002
  circle C4 centre (-106.68, 77.216) radius 1.6002
  point P4 (81.28, 77.216)
  point P5 (106.68, 77.216)
  point P6 (195.58, 77.216)
  point P7 (220.98, 71.12)
  midpoint L1 P4
  horizontal P4 P5
  horizontal P4 P6
  symmetric C1 L2 C4
  symmetric C2 L2 C3
  dimension "d2895" diameter C1 = 3.2004 (= "hole_screw")
  dimension "d2896" distance P4 P5 = 25.4
  dimension "d2897" diameter C2 = 3.2004 (= "hole_screw")
  dimension "d2898" distance P6 P7 = 25.4
sketch "cap_bottom" plane through (0, 0, 894.08) normal (0, 0, 1) x axis (1, 0, 0)
  line L1 (228.6, 508) -> (-228.6, 508)
  line L2 (228.6, 12.192) -> (228.6, 508)
  line L3 (-165.608, 0) -> (165.608, 0)
  line L4 (-228.6, 508) -> (-228.6, 12.192)
  line L5 (-402.336, 508) -> (402.336, 508)
  line L6 (-216.408, 495.808) -> (-216.408, 12.192)
  line L7 (216.408, 495.808) -> (-216.408, 495.808)
  line L8 (216.408, 12.192) -> (216.408, 495.808)
  line L9 (0, 20) -> (0, 2.5)
  line L10 (216.408, 12.192) -> (165.608, 0)
  line L11 (216.408, 12.192) -> (220.98, 12.192)
  line L12 (-216.408, 12.192) -> (-165.608, 0)
  line L13 (-216.408, 12.192) -> (-220.98, 12.192)
  line L14 (228.6, 12.192) -> (220.98, 12.192)
  line L15 (-228.6, 12.192) -> (-216.408, 12.192)
  line L16 (-220.98, 500.38) -> (-220.98, 12.192)
  line L17 (220.98, 500.38) -> (-220.98, 500.38)
  line L18 (220.98, 12.192) -> (220.98, 500.38)
  circle C1 centre (-152.4, 76.2) radius 8.128
  circle C2 centre (-152.4, 76.2) radius 5.207
  circle C3 centre (-152.4, 431.8) radius 8.128
  circle C4 centre (-152.4, 431.8) radius 5.207
  circle C5 centre (152.4, 431.8) radius 8.128
  circle C6 centre (152.4, 431.8) radius 5.207
  circle C7 centre (152.4, 76.2) radius 5.207
  circle C8 centre (152.4, 76.2) radius 8.128
  point P6 (0, 508)
  point P24 (220.98, 12.192)
  point P29 (220.98, 12.192)
  point P26 (-216.408, 12.192)
  point P30 (-216.408, 12.192)
  point P7 (216.408, 12.192)
  point P23 (216.408, 12.192)
  point P8 (-216.408, 12.192)
  point P27 (-220.98, 12.192)
  point P32 (-220.98, 12.192)
  point P35 (220.98, 12.192)
  point P2 (-228.6, 508)
  point P3 (228.6, 508)
  horizontal L1
  vertical L2
  horizontal L3
  vertical L4
  midpoint L1 P6
  midpoint L5 P6
  coincident P24 P29
  perpendicular L2 L14
  coincident P26 P30
  perpendicular L4 L15
  horizontal L7
  vertical L6
  coincident P7 P23
  coincident P8 P30
  vertical L8
  coincident P27 P32
  coincident P29 P35
  dimension "d2838" distance P2 P3 = 457.2 (= "printer_width_adjusted")
  dimension "d3476" distance P6 L7 = 12.192 (= "material_thickness")
extrude "Extrude1" new body sketch "cap_bottom" profile of L3 L6 L7 L8 C1 C2 C3 C4 C5 C6 C7 C8 L10 L11 L12 L13 L16 L17 L18 along normal blind 12.192 (= "material_thickness") bodies "cap_bottom"
extrude "Extrude3" sketch "cap_bottom" profile of C1 C2 C3 C4 C5 C6 C7 C8 no distance stored
sketch "cap_side" plane through (228.6, 0, 0) normal (1, 0, 0) x axis (0, 1, 0)
  line L1 (508, 894.08) -> (0, 894.08)
  line L2 (508, 970.28) -> (508, 894.08)
  line L3 (0, 894.08) -> (0, 919.48)
  line L4 (50.8, 970.28) -> (0, 919.48)
  line L5 (495.808, 894.08) -> (495.808, 970.28)
  line L6 (0, 85.5947) -> (0, 2.9515)
  line L7 (508, -402.336) -> (508, 402.336)
  line L8 (-3.87, 894.08) -> (26.37, 894.08)
  line L9 (177.8, 944.88) -> (152.4, 970.28)
  line L10 (330.2, 944.88) -> (177.8, 944.88)
  line L11 (355.6, 970.28) -> (330.2, 944.88)
  line L12 (355.6, 970.28) -> (508, 970.28)
  line L13 (50.8, 970.28) -> (152.4, 970.28)
  line L14 (12.192, 906.272) -> (12.192, 894.08)
  line L15 (495.808, 906.272) -> (12.192, 906.272)
  line L16 (0, 894.08) -> (0, 817.88)
  line L17 (254, 894.08) -> (254, 906.272)
  line L18 (495.808, 932.18) -> (508, 932.18)
  circle C1 centre (254, 900.176) radius 1.6002
  circle C2 centre (38.1, 900.176) radius 1.6002
  circle C3 centre (469.9, 900.176) radius 1.6002
  circle C4 centre (501.904, 953.3467) radius 1.6002
  circle C5 centre (501.904, 911.0133) radius 1.6002
  point P7 (495.808, 970.28)
  point P8 (495.808, 894.08)
  point P2 (0, 894.08)
  point P10 (0, 85.5947)
  point P3 (508, 894.08)
  point P11 (508, 402.336)
  point P19 (254, 894.08)
  point P20 (254, 944.88)
  point P21 (0, 894.08)
  point P22 (0, 894.08)
  point P23 (12.192, 894.08)
  point P25 (495.808, 906.272)
  point P28 (254, 906.272)
  point P29 (254, 894.08)
  point P30 (254, 900.176)
  point P33 (508, 932.18)
  point P34 (495.808, 932.18)
  point P35 (501.904, 932.18)
  point P36 (501.904, 953.3467)
  point P37 (501.904, 911.0133)
  point P4 (508, 970.28)
  point P5 (0, 919.48)
  point P17 (330.2, 944.88)
  point P18 (355.6, 970.28)
  point P15 (152.4, 970.28)
  point P24 (12.192, 906.272)
  point P38 (508, 894.08)
  horizontal L1
  vertical L2
  horizontal L12
  vertical L3
  coincident P7 L12
  coincident L1 P8
  perpendicular L1 L5
  vertical P2 P10
  vertical P3 P11
  parallel L10 L12
  equal L9 L11
  midpoint L1 P19
  midpoint L10 P20
  vertical P19 P20
  collinear L12 L13
  coincident P21 P22
  coincident P2 P21
  coincident L8 P23
  perpendicular L8 L14
  coincident L5 P25
  horizontal L15
  midpoint L15 P28
  coincident P19 P29
  midpoint L17 P30
  midpoint L2 P33
  midpoint L5 P34
  midpoint L18 P35
  vertical P35 P36
  vertical P35 P37
  dimension "d2850" distance L2 P8 = 12.192 (= "material_thickness")
  dimension "d2853" distance P3 P4 = 76.2
  dimension "d2854" distance P2 P5 = 25.4
  dimension "d2855" angle L3 L4 = 135
  dimension "d2856" distance P17 P18 = 25.4
  dimension "d2857" distance P15 P18 = 203.2
  dimension "d2858" angle L9 L10 = 135
  dimension "d3478" distance P23 P24 = 12.192 (= "material_thickness")
  dimension "d3479" distance P23 L16 = 12.192 (= "material_thickness")
  dimension "d3480" diameter C1 = 3.2004 (= "hole_screw")
  dimension "d3485" diameter C4 = 3.2004 (= "hole_screw")
  dimension "d3486" diameter C5 = 3.2004 (= "hole_screw")
  dimension "d3487" distance P37 P38 = 16.9333 (= "hole_screw_brace_offset / 1.5")
  dimension "d3488" distance P4 P36 = 16.9333 (= "hole_screw_brace_offset / 1.5")
  dimension "d3483" R-Pattern1-uDistance = 215.9
  dimension "d3484" R-Pattern1-vDistance = 0
sketch "cap_back" plane through (0, 508, 0) normal (0, 1, 0) x axis (1, 0, 0)
  line L1 (176.53, -970.28) -> (220.98, -970.28)
  line L2 (0, -894.08) -> (0, -977.646)
  line L3 (220.98, -894.08) -> (0, -894.08)
  line L4 (220.98, -970.28) -> (220.98, -894.08)
  line L5 (127, -394.9505) -> (127, -609.6)
  line L6 (151.13, -944.88) -> (176.53, -970.28)
  line L7 (0, -944.88) -> (151.13, -944.88)
  line L8 (-220.98, -894.08) -> (0, -894.08)
  line L9 (-220.98, -970.28) -> (-220.98, -894.08)
  line L10 (-176.53, -970.28) -> (-220.98, -970.28)
  line L11 (-151.13, -944.88) -> (-176.53, -970.28)
  line L12 (0, -944.88) -> (-151.13, -944.88)
  line L13 (228.6, -894.08) -> (-228.6, -894.08)
  line L14 (-220.98, -906.272) -> (220.98, -906.272)
  circle C1 centre (0, -900.176) radius 1.6002
  circle C2 centre (-190.5, -900.176) radius 1.6002
  circle C3 centre (190.5, -900.176) radius 1.6002
  point P4 (0, -894.08)
  point P8 (0, -894.08)
  point P2 (220.98, -970.28)
  point P10 (228.6, -970.28)
  point P13 (0, -944.88)
  point P16 (-220.98, -970.28)
  point P14 (0, -894.08)
  point P5 (220.98, -894.08)
  point P15 (-220.98, -894.08)
  point P11 (176.53, -970.28)
  point P17 (-176.53, -970.28)
  point P12 (151.13, -944.88)
  point P18 (-151.13, -944.88)
  point P19 (0, -944.88)
  point P22 (0, -900.176)
  point P25 (220.98, -906.272)
  point P26 (-220.98, -906.272)
  point P21 (228.6, -894.08)
  horizontal L1
  vertical L2
  horizontal L3
  vertical L4
  vertical L5
  vertical P4 P8
  horizontal P2 P10
  coincident L2 P13
  perpendicular L2 L7
  symmetric P2 L2 P16
  symmetric P4 L2 P14
  symmetric P5 L2 P15
  symmetric L2 P11 P17
  symmetric L2 P12 P18
  symmetric L2 P13 P19
  coincident P5 L13
  coincident L2 P22
  coincident L4 P25
  coincident L9 P26
  horizontal L14
  dimension "d2861" angle L6 L7 = 135
  dimension "d2862" distance P2 P11 = 44.45 (= "global_cutout_padding")
  dimension "d2863" distance P11 P12 = 25.4
  dimension "d3490" distance P5 P21 = 7.62 (= "material_thickness - dado_material_depth")
  dimension "d3491" diameter C1 = 3.2004 (= "hole_screw")
  dimension "d3492" distance P14 P22 = 6.096 (= "material_thickness / 2")
  dimension "d3497" distance P5 P25 = 12.192 (= "material_thickness")
  dimension "d3495" R-Pattern1-uDistance = 190.5
  dimension "d3496" R-Pattern1-vDistance = 0
extrude "Extrude4" new body sketch "cap_side" profile of L1 L2 L13 L3 L4 L5 L9 L10 L11 L14 L15 C1 C2 C3 C4 C5 no distance stored bodies "cap_side_right"
extrude "Extrude5" sketch "cap_side" profile of L1 L2 L13 L5 L14 L15 C1 C2 C3 C4 C5 blind 4.572 (= "dado_material_depth")
extrude "Extrude6" new body sketch "cap_back" profile of L1 L3 L4 L6 L7 L8 L9 L10 L11 L12 L13 C1 C2 C3 L14 no distance stored bodies "cap_back"
extrude "Extrude7" cut sketch "cap_back" profile of L3 L4 L8 L9 L13 C1 C2 C3 L14 along normal blind 4.572 (= "dado_material_depth")
mirror "Mirror1" mirrorStitchTolerance 0.1016 bodies "cap_side_left"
